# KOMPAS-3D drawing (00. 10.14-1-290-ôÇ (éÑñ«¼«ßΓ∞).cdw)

Views: Вид 1
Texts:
  Smirnov NIkita
  Схема Э3
  Текст на чертеже
  Размерные надписи
  Шероховатость
  Линия-выноска #1
  Линия-выноска #2
  Линия-выноска #3
  Отклонения формы и база
  Заголовок таблицы
  Ячейка таблицы
  Стрелка вида
  Обозначение изменения
  Фигурная скобка
  Номер узла
  Марка координационной оси
  VRCB
  Выносная надпись
  Обозначение узла
  Марка/позиционное обозначение с линией-выноской
  Марка/позиционное обозначение на линии
  Марка/позиционное обозначение без линии-выноски
  Лит-Масса-Масштаб
  Материал-Предприятие
  Normal
  Title Specification
  Body Specification ( left align )
  Body Specificaton ( centered )
  Обычный
  Термин
  Список определений
  Адрес
  Цитаты
  Форматированный
  Courier New
  Z-конец формы
  Z-начало формы
  Additional DXF text style 0
  heading 1
  Знак Знак Знак Знак Знак Знак
  Verdana
  Абзац Знак
  Body Text
  Body Text 3
  Title
  Без имени
  ТекстШаг1
  Txt
  Шрифт 2.5
  Заголовки
  Simplex
  txt
  MS Sans Serif
  TXT
  Подпись в квадратике
  цепи
  ссылки
  табл
  Тексты. 3,2
  ЗОНА_привяз
  текст переноса
  Маркировка
  клеммы, контакты
  тексты табл
  ООббыыччнныыйй
  ТТееррммиинн
  ССппииссоокк ооппррееддееллеенниийй
  ААддрреесс
  ЦЦииттааттыы
  ФФооррммааттиирроовваанннныыйй
  Z-ккооннеецц ффооррммыы
  Z-ннааччааллоо ффооррммыы
  heading 2
  AGOpus
  footer
  russ
  Аппараты
  подписи
  Денис
  heading 8
  heading 3
  heading 6
  heading 7
  heading 4
  heading 5
  heading 9
  Клеммник текст
  rustxt
  маркировка
  Состав чартежа
  ячейка табл.
  Table Contents
  Table Heading
  Tahoma
  Ссылки
  Пояснения
  Definition Term
  Definition List
  Address
  Blockquote
  Preformatted
  z-Bottom of Form
  z-Top of Form
  header
  Текст 3,5
  ГОСТ_МНЕ
  ESK - Обозначение
  Body Text Indent 3
  Основной текст с отступом 3
  Новое оборудование
  GOST 2.304 type A
  style2
  HeliosLight
  Pa3
  Pa1
  RUSTXT
  ISOCP
  NormalParagraphStyle
  Три с половиной
  CNBNDG+TimesNewRoman
  Subtitle
  Adobe Gothic Std B
  Схема
  ВО.2
  ВО.1
  Шкаф 5Р. ТН 110 кВ, ТН 6 кВ и элегаз. Схема электрическая принципиальная
  Шкаф 5Р. ТН 110 кВ, ТН 6 кВ и элегаз. Схема рядов зажимов
  Шкаф сигнализации РЗТ. Чертеж общего вида
  Шкаф сигнализации РЗТ. Схема электрическая принципиальная
  Шкаф сигнализации РЗТ. Схема рядов зажимов
  Шкаф 5Р. ТН 110 кВ, ТН 6 кВ и элегаз. Чертеж общего вида
  Таблица УК и технических данных аппаратуры по заказу
  Сводная попанельная спецификация
  Изм. 1 (л.1)
  Изм.1
  Ведомость рабочих чертежей комплекта 10/14-1-290-УА
  CONTINUOUS0
  Принципиальная схема управления, автоматики
  и сигнализации ВЛ - 110 кВ W5G(W6G)
  АББЧ.656.453.009 Э3-РЗА
  Н.контр.
  Разраб.
  Схема организации сигнально-
  оперативных  шинок в помещении ОПУ
  Реконструкция ПС №527
  с заменой силовых трансформаторов
  и вводом нового ЗРУ-10 кВ
  ПС 527 110/10кВ
  Ведомость рабочих чертежей
  Борисов
  Алдошина
  ГИП
  Маленкин
Dimensions and other numbers on the sheet: 10/14-1-290-УА; 7; 1,8; 2,5; 2.5; 3,2_; 3,2_зона не привяз; 3,2 (надписи); 2,5_3; 2,5 (контакты, клеммы); 2,5_01; 3,5_01; 2,3_; 5_заголовок; 3,5_tabl; 2,5 грязносинь; 3,2; 3,5; 3.5; 5; 3,2 элементы; 3,2 линия; 3,2 таблица; 3.2 маркировка; 2.5_Э5_надписи; 2.5_Э5_ссылки; 2.5_кабель; 3.2; 2.5 надписи; 3,2 (Зоны); 3.2 (текст); 2.5 курсив; 5,0_белый_подчёркнутый; 3.2 фиол; 3 и 5; 4 листа; 1 лист; 3 листа; 2 листа; 4; 1:1; 1; 11.12; 11.09/86.009-290-УА-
